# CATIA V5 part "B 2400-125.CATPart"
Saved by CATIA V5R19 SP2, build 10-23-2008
Part number: B 2400-125
Bounding box of the stored display mesh (mm): x -37.351 to 37.351, y -37.351 to 37.351, z 0 to 360
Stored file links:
  C:\Users\Bora\Desktop\3D Katı model\B serisi\B 2400\B 2400-125.CATPart
  C:\Program Files\Dassault Systemes\B19\intel_a\reffiles\standard\MetricThickPitch.txt
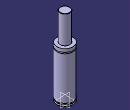
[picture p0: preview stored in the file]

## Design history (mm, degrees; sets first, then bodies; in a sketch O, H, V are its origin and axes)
Body1 (main body)
  Sketch1 on yz-plane, origin (0, 0, 0), H (0, 1, 0), V (0, 0, 1)
    point P3 (22.5, 359)
    point P5 (22.5, 359)
    point P10 (37.5, 211.5)
    point P11 (37.5, 216.5)
    point P13 (37.5, 216.5)
    point P14 (37.5, 211.5)
    line L1 (37.5, 0) -> (37.5, 8)
    line L2 (22.5, 359) -> (22.5, 232)
    arc A1 centre (21.5, 359) radius 1 from (22.5, 359) to (21.5, 360) ccw
    line L3 (33.5, 13) -> (33.5, 8)
    line L4 (37.5, 13) -> (37.5, 211.5)
    line L5 (37.5, 216.5) -> (37.5, 232)
    arc A2 centre (37.5, 214) radius 2.5 from (37.5, 216.5) to (37.5, 211.5) ccw
    line L6 (21.5, 360) -> (0, 360)
    point P15 (0, 360)
    line L7 (22.5, 232) -> (37.5, 232)
    line L8 (0, 0) -> (37.5, 0)
    line L9 (33.5, 13) -> (37.5, 13)
    line L10 (33.5, 8) -> (37.5, 8)
    coincidence: P15 V, P3 P5, P10 P14, P11 P13
    tangency: L6 A1
    horizontal: L7 H, L8 H, L9 H, L10 H
  Shaft1: profile Sketch1, axis Sketch1.V, angle 360
  Sketch2 on face of Shaft1 from Sketch1.L8, origin (0, 0, 0), H (1, 0, 0), V (0, -1, 0)
    point P1 (20, 0)
    distance V P1 = 20
  Hole1: placed by Sketch2, at (20, 0, 0) direction (0, 0, 1), diameter 6.647, depth 13, threaded "M8", thread diameter 8, thread depth 13, pitch 1.25
  CircPattern1: of Hole1, instances 4, angular step 90, axis from xy-plane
